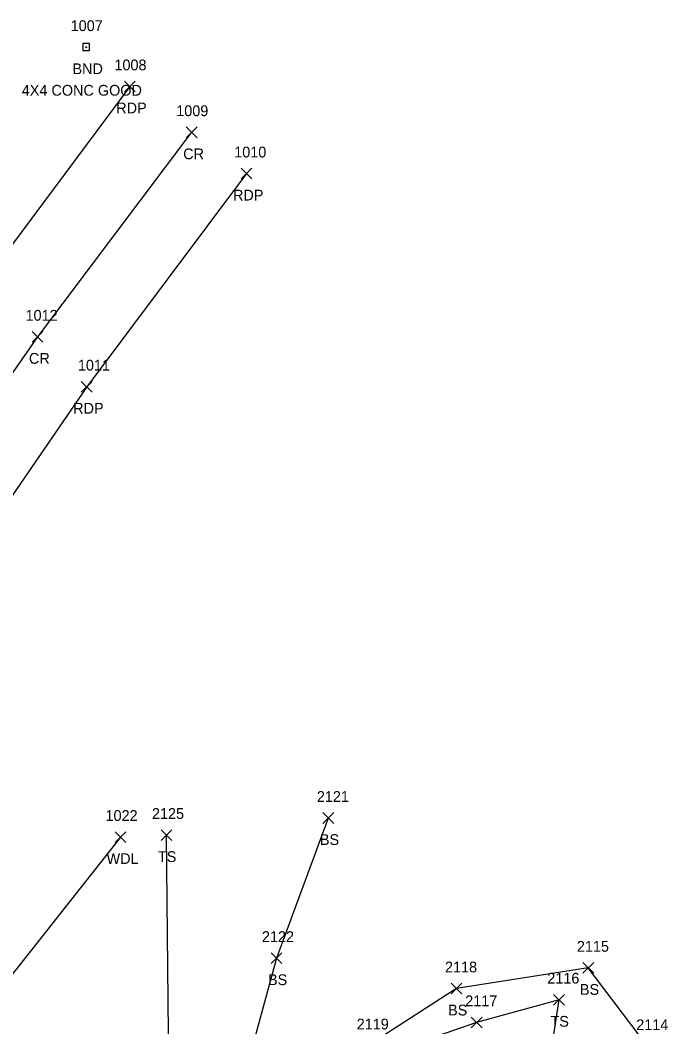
# Model space of a CAD drawing. Extents: x 1551995 to 1555700, y 777276 to 783130.
# Drawn here: x 1555066.5 to 1555186.7, y 778211.4 to 778398.3 of the extents above; entities that cross this region are included whole.
import ezdxf

# ---------------------------------------------------------------- set-up
doc = ezdxf.new("R2010")
doc.units = 0
for name, color, linetype in [('L_A', 7, 'Continuous'), ('L_I', 7, 'Continuous'), ('L_TIC', 7, 'Continuous'), ('LAWA', 7, 'Continuous'), ('LELB', 7, 'Continuous'), ('Level 18', 7, 'Continuous'), ('M_A', 7, 'Continuous'), ('M_C', 7, 'Continuous'), ('M_I', 7, 'Continuous'), ('P_A', 7, 'Continuous'), ('P_I', 7, 'Continuous'), ('P_TIC', 7, 'Continuous'), ('PET', 7, 'Continuous'), ('PRC', 7, 'Continuous')]:
    doc.layers.add(name, color=color, linetype=linetype)

msp = doc.modelspace()

# ---------------------------------------------------------------- linework, layer by layer
at = {"layer": 'L_TIC'}
for points in [[(1555122.69, 778249.13), (1555124.69, 778251.13)], [(1555124.69, 778249.13), (1555122.69, 778251.13)], [(1555084.12, 778245.6), (1555086.12, 778247.6)], [(1555086.12, 778245.6), (1555084.12, 778247.6)], [(1555092.66, 778245.97), (1555094.66, 778247.97)], [(1555094.66, 778245.97), (1555092.66, 778247.97)], [(1555113.06, 778223.11), (1555115.06, 778225.11)], [(1555115.06, 778223.11), (1555113.06, 778225.11)], [(1555170.93, 778221.3), (1555172.93, 778223.3)], [(1555172.93, 778221.3), (1555170.93, 778223.3)], [(1555146.47, 778217.47), (1555148.47, 778219.47)], [(1555148.47, 778217.47), (1555146.47, 778219.47)], [(1555165.5, 778215.38), (1555167.5, 778217.38)], [(1555167.5, 778215.38), (1555165.5, 778217.38)], [(1555150.21, 778211.18), (1555152.21, 778213.18)], [(1555152.21, 778211.18), (1555150.21, 778213.18)]]:
    msp.add_lwpolyline(points, dxfattribs=at)
at = {"layer": 'LAWA'}
msp.add_lwpolyline([(1555085.12, 778246.6), (1555062.11, 778217.51), (1555036.75, 778197.89), (1555030.02, 778178.79), (1555023.09, 778154.13), (1555005.22, 778133.85), (1555000.72, 778121.06), (1554983.85, 778091.44), (1554975.19, 778092.03), (1554970.99, 778074.93), (1554967.22, 778059.88), (1554967.17, 778023.98), (1554956.28, 777979.25), (1554949.24, 777950.5), (1554942.15, 777917.97), (1554937.88, 777884.35), (1554924.17, 777845.95), (1554911.99, 777797.39)], dxfattribs=at)
at = {"layer": 'LELB'}
for points in [[(1555123.69, 778250.13), (1555114.06, 778224.11), (1555108, 778201.88)], [(1555135, 778132.57), (1555116.51, 778141.47), (1555118.7, 778168.03), (1555150.02, 778188.76), (1555163.14, 778194.26), (1555166.5, 778216.38), (1555151.21, 778212.18), (1555132.34, 778205.59), (1555108, 778201.88), (1555094.09, 778204.05), (1555093.66, 778246.97)], [(1555090.96, 778044.64), (1555101.27, 778057.41), (1555102.13, 778063.02), (1555118.39, 778106.13), (1555115.04, 778128.59), (1555116.51, 778141.47), (1555141.3, 778165.52), (1555169.36, 778182.3), (1555182.25, 778189.59), (1555182.94, 778207.75), (1555171.93, 778222.3), (1555147.47, 778218.47), (1555131.09, 778207.87), (1555108, 778201.88)]]:
    msp.add_lwpolyline(points, dxfattribs=at)
at = {"layer": 'Level 18'}
for p, q in [((1555079.38, 778393.94), (1555078.13, 778393.94)), ((1555078.13, 778393.94), (1555078.13, 778392.69)), ((1555079.38, 778393.94), (1555078.13, 778393.94)), ((1555078.13, 778393.94), (1555078.13, 778392.69)), ((1555078.13, 778392.69), (1555079.38, 778392.69)), ((1555078.13, 778392.69), (1555079.38, 778392.69)), ((1555079.38, 778392.69), (1555079.38, 778393.94)), ((1555079.38, 778392.69), (1555079.38, 778393.94))]:
    msp.add_line(p, q, dxfattribs=at)
msp.add_circle((1555078.74, 778393.28), 0.0833, dxfattribs=at)
at = {"layer": 'P_TIC'}
for points in [[(1555085.85, 778384.99), (1555087.85, 778386.99)], [(1555087.85, 778384.99), (1555085.85, 778386.99)], [(1555097.33, 778376.48), (1555099.33, 778378.48)], [(1555099.33, 778376.48), (1555097.33, 778378.48)], [(1555107.52, 778368.81), (1555109.52, 778370.81)], [(1555109.52, 778368.81), (1555107.52, 778370.81)], [(1555068.71, 778338.49), (1555070.71, 778340.49)], [(1555070.71, 778338.49), (1555068.71, 778340.49)], [(1555077.86, 778329.23), (1555079.86, 778331.23)], [(1555079.86, 778329.23), (1555077.86, 778331.23)]]:
    msp.add_lwpolyline(points, dxfattribs=at)
at = {"layer": 'PET'}
for points in [[(1555086.85, 778385.99), (1555058.53, 778347.95), (1555034.13, 778312.76), (1555016.69, 778284.76), (1554990.68, 778240.38), (1554968.05, 778196.33), (1554953.03, 778164.25), (1554940.37, 778132.83), (1554930.99, 778106.02), (1554923.77, 778083.63), (1554909.85, 778036.75), (1554900.04, 777995.37), (1554891.67, 777961.45), (1554881.9, 777917.03), (1554872.92, 777875.28), (1554862.74, 777826.66), (1554851.19, 777774.32)], [(1555108.52, 778369.81), (1555078.86, 778330.23), (1555056.92, 778298.28), (1555038.33, 778268.72), (1555013, 778223.52), (1554996, 778190.4), (1554978.91, 778154.53), (1554967.24, 778125.11), (1554957.25, 778096.67), (1554950.17, 778073.38), (1554937.06, 778028.22), (1554926.8, 777988.52), (1554918.72, 777954.59), (1554908.46, 777910.08), (1554899.75, 777869.14), (1554889.9, 777822.39), (1554877.4, 777767.74)]]:
    msp.add_lwpolyline(points, dxfattribs=at)
at = {"layer": 'PRC'}
msp.add_lwpolyline([(1555098.33, 778377.48), (1555069.71, 778339.49), (1555045.49, 778304.7), (1555028.73, 778278.05), (1555002.89, 778234.08), (1554980, 778189.5), (1554966.22, 778159.18), (1554954.38, 778129.46), (1554944.07, 778101.03), (1554941.59, 778092.54), (1554937.34, 778078.77), (1554924.27, 778032.77), (1554914.16, 777991.62), (1554905.84, 777957.86), (1554895.98, 777913.96), (1554886.88, 777872.59), (1554876.72, 777824.26), (1554864.6, 777770.35)], dxfattribs=at)

# ---------------------------------------------------------------- texts
at = {"layer": 'L_A'}
for s, p in [('BS', (1555122.13, 778245.13)), ('WDL', (1555082.54, 778241.6)), ('TS', (1555092.07, 778241.97)), ('BS', (1555112.5, 778219.11)), ('BS', (1555170.37, 778217.3)), ('BS', (1555145.91, 778213.47)), ('TS', (1555164.91, 778211.38))]:
    msp.add_text(s, height=2, dxfattribs=at).set_placement(p)
at = {"layer": 'L_I'}
for s, p in [('2121', (1555121.56, 778253.13)), ('1022', (1555082.35, 778249.6)), ('2125', (1555090.97, 778249.97)), ('2122', (1555111.37, 778227.11)), ('2115', (1555169.81, 778225.3)), ('2118', (1555145.34, 778221.47)), ('2116', (1555164.32, 778219.38)), ('2117', (1555149.09, 778215.18)), ('2119', (1555128.96, 778210.87)), ('2114', (1555180.82, 778210.75))]:
    msp.add_text(s, height=2, dxfattribs=at).set_placement(p)
at = {"layer": 'M_A'}
msp.add_text('BND', height=2, dxfattribs=at).set_placement((1555076.22, 778388.28))
at = {"layer": 'M_C'}
msp.add_text('4X4 CONC GOOD', height=2, dxfattribs=at).set_placement((1555066.81, 778384.28))
at = {"layer": 'M_I'}
msp.add_text('1007', height=2, dxfattribs=at).set_placement((1555075.88, 778396.28))
at = {"layer": 'P_A'}
for s, p in [('RDP', (1555084.34, 778380.99)), ('CR', (1555096.76, 778372.48)), ('RDP', (1555106, 778364.81)), ('CR', (1555068.14, 778334.49)), ('RDP', (1555076.35, 778325.23))]:
    msp.add_text(s, height=2, dxfattribs=at).set_placement(p)
at = {"layer": 'P_I'}
for s, p in [('1008', (1555084, 778388.99)), ('1009', (1555095.47, 778380.48)), ('1010', (1555106.23, 778372.81)), ('1012', (1555067.51, 778342.49)), ('1011', (1555077.22, 778333.23))]:
    msp.add_text(s, height=2, dxfattribs=at).set_placement(p)

doc.saveas('drawing.dxf')
